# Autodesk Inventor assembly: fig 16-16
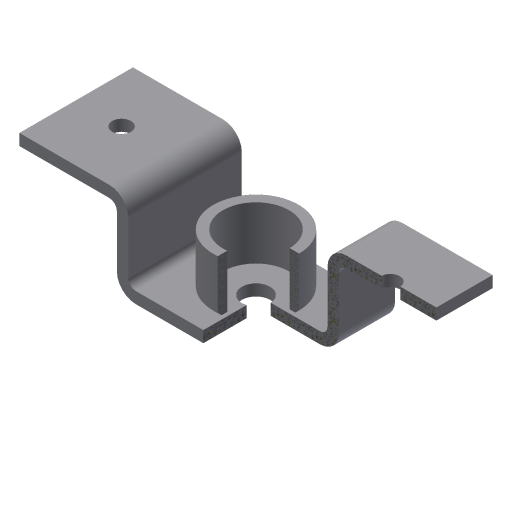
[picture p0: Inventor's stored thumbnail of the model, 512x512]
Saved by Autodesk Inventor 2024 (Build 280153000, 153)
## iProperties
Created: 2005-03
Part Number: fig 16-16
Document SubType Name: Weldment
Designer: CADCIM
Manufacturer: Standard
Standards Organization: Custom
Author: CADCIM
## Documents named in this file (3)
- D:\PROJECTS\Project 2023\RESOURCES INVENTOR 2024\RESOURCES INVENTOR 2024\Inventor_2023_Part\Inventor_2024_Part\c16_Inv_2024_prt\fig 16-16\fig 16-16.iam
- D:\PROJECTS\Project 2023\RESOURCES INVENTOR 2024\RESOURCES INVENTOR 2024\Inventor_2023_Part\Inventor_2024_Part\c16_Inv_2024_prt\fig 16-16\Bracket.ipt
- D:\PROJECTS\Project 2023\RESOURCES INVENTOR 2024\RESOURCES INVENTOR 2024\Inventor_2023_Part\Inventor_2024_Part\c16_Inv_2024_prt\fig 16-16\cylinder.ipt
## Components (2 placed, 2 different names)
1. Bracket:1 — Insert:1
2. cylinder:1 — Insert:1
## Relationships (1: Insert 1)
- Insert:1: Bracket:1 ↔ cylinder:1
